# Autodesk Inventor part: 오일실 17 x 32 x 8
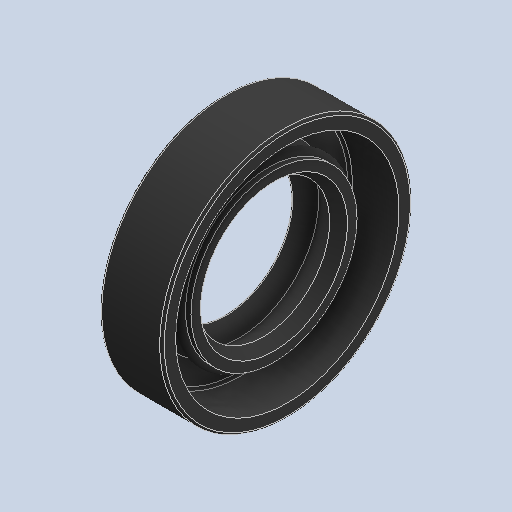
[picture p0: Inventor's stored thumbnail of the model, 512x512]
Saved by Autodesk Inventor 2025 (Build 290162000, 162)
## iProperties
Created: 2024-07
Part Number: 오일실 17 x 32 x 8
Material: 고무
Description: 오일-실
Document SubType Name: Modeling
Designer: SAMSUNG
Density: 0.93 g/cm^3
Appearance: 기본값
Author: jhkim
Sending System: Autodesk Inventor 2025
Preprocessor: ST-DEVELOPER v20
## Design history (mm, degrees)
feature "Solid1"
node "솔리드1"
